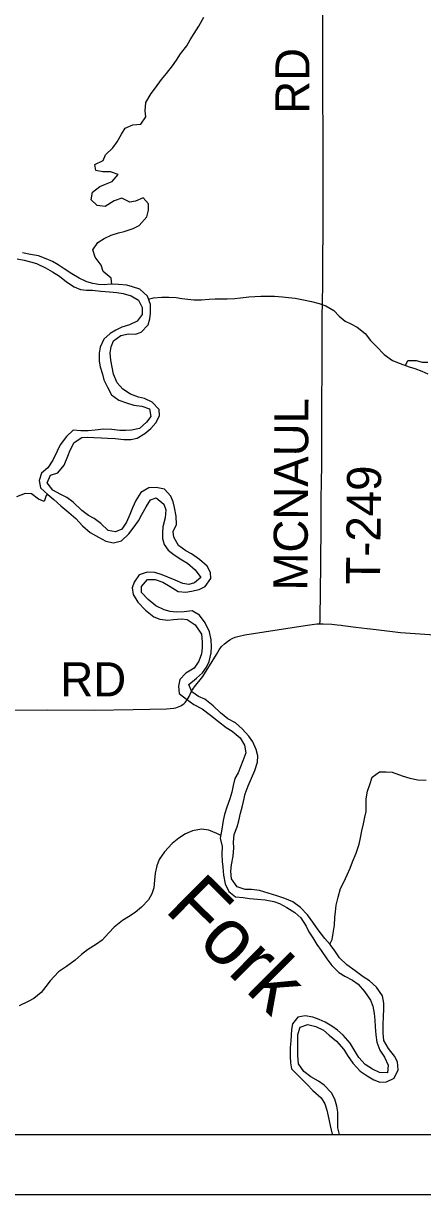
# Model space of a CAD drawing. Extents: x 0 to 70.2, y 0 to 31.4.
# Drawn here: x 5.768 to 6.434, y 14 to 15.952 of the extents above; entities that cross this region are included whole.
import ezdxf

# ---------------------------------------------------------------- set-up
doc = ezdxf.new("R2010")
doc.units = 0
for name, color, linetype in [('GM_X_Major_River', 7, 'Continuous'), ('GM_X_Major_River_Text', 7, 'Continuous'), ('GM_X_Minor_River', 7, 'Continuous'), ('GM_X_Section_Text', 7, 'Continuous'), ('GM_X_Township_Road', 7, 'Continuous'), ('GM_X_Township_Road_Text', 7, 'Continuous'), ('SH_Cut_Line', 7, 'Continuous'), ('SH_Data', 7, 'Continuous')]:
    doc.layers.add(name, color=color, linetype=linetype)

msp = doc.modelspace()

# ---------------------------------------------------------------- linework, layer by layer
at = {"layer": 'GM_X_Major_River'}
for points in [[(5.7581, 15.56), (5.7698, 15.5577), (5.78, 15.555), (5.7903, 15.552), (5.8051, 15.5448), (5.8172, 15.538), (5.8289, 15.5308), (5.8403, 15.5213), (5.8532, 15.5133), (5.8634, 15.5084), (5.8737, 15.5076), (5.8839, 15.5073), (5.8975, 15.5061), (5.9119, 15.505), (5.9245, 15.5035), (5.9347, 15.502), (5.948, 15.4982), (5.9601, 15.4906), (5.9665, 15.4784), (5.9665, 15.4671), (5.9582, 15.4557), (5.9453, 15.4496), (5.9328, 15.4458), (5.9225, 15.4409), (5.913, 15.4352), (5.9028, 15.4257), (5.8964, 15.4128), (5.8948, 15.4026), (5.8948, 15.3893), (5.8963, 15.3798), (5.9001, 15.3677), (5.9028, 15.3582), (5.9088, 15.3457), (5.9156, 15.3328), (5.9274, 15.3244), (5.9403, 15.3195), (5.9524, 15.3161), (5.9661, 15.3142), (5.9789, 15.3097), (5.9812, 15.2968), (5.9736, 15.2873), (5.9619, 15.2767), (5.9486, 15.274), (5.9391, 15.2736), (5.9293, 15.2736), (5.916, 15.2751), (5.9023, 15.2759), (5.8879, 15.2744), (5.8766, 15.2732), (5.8641, 15.2729), (5.8515, 15.274), (5.8402, 15.2638)], [(5.8659, 15.2619), (5.8754, 15.2626), (5.8857, 15.2622), (5.8985, 15.2615), (5.9084, 15.2607), (5.9217, 15.2603), (5.9357, 15.2585), (5.9478, 15.2585), (5.9581, 15.2611), (5.971, 15.2687), (5.9808, 15.277), (5.9892, 15.2865), (5.9956, 15.2983), (5.9949, 15.3085), (5.9831, 15.3207), (5.9702, 15.3271), (5.9604, 15.3294), (5.9471, 15.3343), (5.9342, 15.3423), (5.9248, 15.3533), (5.9187, 15.3677), (5.9164, 15.3794), (5.9142, 15.3908), (5.913, 15.403), (5.9146, 15.4132), (5.9187, 15.4231), (5.9309, 15.4318), (5.9438, 15.4348), (5.9551, 15.4344), (5.965, 15.4375), (5.9764, 15.45), (5.979, 15.4599), (5.9805, 15.4693), (5.9806, 15.4838), (5.9753, 15.4978), (5.9628, 15.5092), (5.9502, 15.5133), (5.9408, 15.5156), (5.9271, 15.5171), (5.9138, 15.5175), (5.9032, 15.5167), (5.8938, 15.5171), (5.8843, 15.5186), (5.8744, 15.5213), (5.8615, 15.5274), (5.8494, 15.5346), (5.8365, 15.5429), (5.8263, 15.5497), (5.8168, 15.5551), (5.8066, 15.56), (5.7937, 15.5649), (5.7804, 15.5672), (5.7668, 15.5695)], [(5.8402, 15.2638), (5.8299, 15.2497), (5.825, 15.2391), (5.8174, 15.2239), (5.8094, 15.2114), (5.7988, 15.2027), (5.7946, 15.1902), (5.7969, 15.178), (5.809, 15.1667), (5.8193, 15.1587), (5.831, 15.1481), (5.8443, 15.1367), (5.8556, 15.1268), (5.867, 15.1147), (5.8795, 15.1037), (5.8935, 15.0961), (5.9057, 15.0893), (5.9185, 15.0862), (5.9318, 15.0897), (5.9443, 15.1014), (5.9515, 15.1109), (5.9603, 15.123), (5.966, 15.1337), (5.9732, 15.1466), (5.9804, 15.1583), (5.9899, 15.1614), (6.0027, 15.1507), (6.0062, 15.1413), (6.005, 15.128), (6.0012, 15.1132), (6.0004, 15.1037), (6.0004, 15.0938), (6.0031, 15.0836), (6.0099, 15.0741), (6.0198, 15.0662), (6.0326, 15.0582), (6.0421, 15.0525), (6.0546, 15.0415), (6.0641, 15.0286), (6.0539, 15.0195), (6.0444, 15.0169), (6.0345, 15.0184), (6.0213, 15.0244), (6.0095, 15.029), (6, 15.0328), (5.9875, 15.0369), (5.9746, 15.0373), (5.9617, 15.0332), (5.953, 15.021), (5.95, 15.0112), (5.9515, 15.0005), (5.9591, 14.9873), (5.9719, 14.9744), (5.986, 14.963), (5.9958, 14.9592), (6.0091, 14.9577), (6.0186, 14.9584), (6.0318, 14.9596), (6.0413, 14.9584), (6.055, 14.9497), (6.0656, 14.9342), (6.0667, 14.9216), (6.0667, 14.9114), (6.0652, 14.9015), (6.061, 14.889), (6.053, 14.8773), (6.0394, 14.8689), (6.0295, 14.8587), (6.0268, 14.8477), (6.0284, 14.8352), (6.0405, 14.8257), (6.0526, 14.817), (6.0663, 14.8098), (6.0803, 14.7991), (6.0935, 14.7885), (6.1068, 14.7783), (6.1163, 14.7726), (6.1299, 14.7616), (6.1371, 14.7491), (6.1394, 14.7362), (6.1341, 14.7229), (6.1306, 14.713), (6.1265, 14.7032), (6.1212, 14.6933), (6.1181, 14.6819), (6.1158, 14.6709), (6.1128, 14.6599), (6.1075, 14.6459), (6.1037, 14.6334), (6.1014, 14.6235), (6.0991, 14.6091), (6.0968, 14.5939), (6.0999, 14.5803), (6.0995, 14.5674), (6.0999, 14.5553), (6.101, 14.5458), (6.1021, 14.5325), (6.1048, 14.5181), (6.1112, 14.5052), (6.1222, 14.4965), (6.1351, 14.495)], [(6.1487, 14.5086), (6.1381, 14.5086), (6.1249, 14.5128), (6.1154, 14.5261), (6.1146, 14.5393), (6.1154, 14.5499), (6.1184, 14.564), (6.1196, 14.578), (6.1188, 14.5875), (6.12, 14.6), (6.1249, 14.6129), (6.1279, 14.6232), (6.1306, 14.636), (6.1333, 14.6455), (6.1355, 14.655), (6.1382, 14.6679), (6.1435, 14.6812), (6.1541, 14.707), (6.1587, 14.721), (6.1591, 14.7316), (6.1568, 14.7419), (6.1508, 14.7544), (6.1443, 14.7639), (6.1333, 14.7764), (6.122, 14.7866), (6.1091, 14.7931), (6.097, 14.8029), (6.0848, 14.8147), (6.0708, 14.8257), (6.0602, 14.8302), (6.0492, 14.8382), (6.0443, 14.85), (6.0572, 14.861), (6.067, 14.8697), (6.0735, 14.8792), (6.078, 14.8887), (6.0815, 14.9031), (6.0819, 14.9133), (6.0815, 14.9247), (6.0785, 14.9383), (6.0716, 14.9528), (6.0622, 14.966), (6.0497, 14.9729), (6.0364, 14.9713), (6.0231, 14.971), (6.0133, 14.9721), (6.0034, 14.9747), (5.9894, 14.9812), (5.9765, 14.9918), (5.9655, 15.0036), (5.9651, 15.0134), (5.9754, 15.0252), (5.9883, 15.0252), (6.0012, 15.0206), (6.0133, 15.0138), (6.0265, 15.0055), (6.0391, 15.0043), (6.0489, 15.0059), (6.0614, 15.0085), (6.0717, 15.0134), (6.0808, 15.0271), (6.0804, 15.037), (6.0751, 15.0476), (6.0622, 15.0586), (6.0486, 15.0681), (6.0391, 15.073), (6.0273, 15.0817), (6.019, 15.0957), (6.0183, 15.1052), (6.0236, 15.117), (6.0232, 15.1306), (6.0206, 15.145), (6.0179, 15.1545), (6.0141, 15.1644), (6.0035, 15.1758), (5.9899, 15.1788), (5.9774, 15.178), (5.9645, 15.1701), (5.9561, 15.1572), (5.9504, 15.1447), (5.9459, 15.1337), (5.9402, 15.1211), (5.9326, 15.1094), (5.922, 15.1045), (5.9098, 15.1067), (5.8977, 15.1185), (5.8863, 15.1268), (5.8769, 15.1318), (5.8659, 15.1401), (5.8515, 15.1541), (5.8409, 15.1621), (5.831, 15.167), (5.8174, 15.1742), (5.8083, 15.1864), (5.8136, 15.1989), (5.8257, 15.2031), (5.8363, 15.2156), (5.8424, 15.2308), (5.8462, 15.2406), (5.8531, 15.2535), (5.8659, 15.2619)], [(6.2957, 14.1), (6.293, 14.1115), (6.2926, 14.1255), (6.2926, 14.1373), (6.2911, 14.1472), (6.2877, 14.1593), (6.2824, 14.1695), (6.2699, 14.1824), (6.2604, 14.1893), (6.2479, 14.1961), (6.2358, 14.2052), (6.227, 14.2181), (6.2263, 14.2317), (6.2259, 14.2454), (6.2263, 14.256), (6.2263, 14.2666), (6.2297, 14.2788), (6.2426, 14.2833), (6.2563, 14.2803), (6.2688, 14.2738), (6.2783, 14.2659), (6.2904, 14.2556), (6.3029, 14.2416), (6.3089, 14.2321), (6.318, 14.2188), (6.3298, 14.2056), (6.3419, 14.198), (6.3529, 14.1912), (6.3627, 14.1874), (6.3737, 14.1878), (6.3866, 14.1942), (6.3931, 14.2079), (6.392, 14.2211), (6.387, 14.2306), (6.3772, 14.2435), (6.3696, 14.2568), (6.3681, 14.2693), (6.3685, 14.2833), (6.3689, 14.2966), (6.3693, 14.3095), (6.3696, 14.319), (6.3674, 14.3315), (6.3575, 14.3459), (6.3458, 14.3565), (6.3348, 14.363), (6.3219, 14.3728), (6.3075, 14.3831), (6.2954, 14.3945), (6.2878, 14.4062), (6.2798, 14.4168), (6.2711, 14.4267), (6.2602, 14.4415), (6.2511, 14.454), (6.2423, 14.4661), (6.2306, 14.4787), (6.2177, 14.4878), (6.2045, 14.4938), (6.1912, 14.498), (6.1624, 14.5071), (6.1487, 14.5086)], [(6.1351, 14.495), (6.1453, 14.4938), (6.1586, 14.4923), (6.1715, 14.4912), (6.1863, 14.4885), (6.1957, 14.4851), (6.2079, 14.4783), (6.2211, 14.4703), (6.231, 14.4612), (6.2397, 14.4476), (6.2446, 14.4377), (6.251, 14.4282), (6.2575, 14.4168), (6.2647, 14.4066), (6.2742, 14.3929), (6.2829, 14.3819), (6.2946, 14.3702), (6.3045, 14.3641), (6.317, 14.3573), (6.3264, 14.3508), (6.3374, 14.3387), (6.3473, 14.3243), (6.3511, 14.3141), (6.3533, 14.3019), (6.3545, 14.2909), (6.3552, 14.2795), (6.356, 14.2663), (6.3579, 14.2541), (6.3628, 14.2409), (6.3704, 14.2291), (6.3768, 14.2158), (6.3756, 14.2029), (6.3624, 14.2037), (6.3506, 14.209), (6.3385, 14.217), (6.3279, 14.2287), (6.3215, 14.2386), (6.3135, 14.2522), (6.3018, 14.2659), (6.2923, 14.2742), (6.2828, 14.2807), (6.2718, 14.2875), (6.2616, 14.2917), (6.251, 14.2955), (6.2381, 14.2977), (6.226, 14.2958), (6.2172, 14.2845), (6.2157, 14.275), (6.2149, 14.2655), (6.2142, 14.256), (6.2134, 14.245), (6.2134, 14.2302), (6.2138, 14.2196), (6.2157, 14.2097), (6.2418, 14.1836), (6.2513, 14.1737), (6.2649, 14.1612), (6.271, 14.151), (6.2744, 14.1407), (6.2778, 14.1255), (6.2808, 14.1126), (6.2831, 14.1009), (6.2833, 14.1)]]:
    msp.add_lwpolyline(points, dxfattribs=at)
at = {"layer": 'GM_X_Minor_River'}
for points in [[(5.9159, 15.5174), (5.915, 15.5274), (5.9017, 15.5384), (5.8979, 15.549), (5.8881, 15.5623), (5.8843, 15.5748), (5.8923, 15.5869), (5.9029, 15.5934), (5.915, 15.5991), (5.9272, 15.6029), (5.9366, 15.6051), (5.9514, 15.6104), (5.9617, 15.6154), (5.9742, 15.6298), (5.9772, 15.6408), (5.9769, 15.6514), (5.9681, 15.6616), (5.9552, 15.656), (5.9458, 15.6544), (5.9325, 15.6609), (5.9196, 15.6567), (5.9048, 15.6472), (5.8912, 15.6484), (5.8817, 15.6582), (5.8836, 15.6707), (5.8957, 15.6802), (5.9052, 15.684), (5.9162, 15.6886), (5.9265, 15.7003), (5.9136, 15.7049), (5.9011, 15.7049), (5.8893, 15.7068), (5.8874, 15.717), (5.9014, 15.7235), (5.9056, 15.7329), (5.9178, 15.7447), (5.9246, 15.7546), (5.9322, 15.7678), (5.9379, 15.7773), (5.9508, 15.7834), (5.9644, 15.7845), (5.9724, 15.7963), (5.9716, 15.8065), (5.9724, 15.8206), (5.9815, 15.8354), (5.9887, 15.8448), (5.9986, 15.8589), (6.0069, 15.8687), (6.0168, 15.8813), (6.024, 15.8911), (6.0304, 15.9014), (6.0407, 15.915), (6.0464, 15.9249), (6.0532, 15.9355), (6.0608, 15.9476), (6.0691, 15.9624)], [(5.9773, 15.4924), (5.9855, 15.4948), (5.9995, 15.4959), (6.0109, 15.4959), (6.023, 15.4951), (6.0325, 15.4936), (6.0424, 15.4925), (6.0526, 15.4917), (6.0655, 15.4917), (6.0784, 15.4925), (6.0882, 15.4929), (6.1083, 15.4929), (6.1208, 15.4936), (6.1303, 15.4948), (6.1443, 15.4963), (6.1546, 15.497), (6.1641, 15.4974), (6.1769, 15.4978), (6.1872, 15.4974), (6.2004, 15.4967), (6.2103, 15.4955), (6.2217, 15.494), (6.2353, 15.4914), (6.2486, 15.4887), (6.2615, 15.4853), (6.2725, 15.4815), (6.2861, 15.4735), (6.2952, 15.4641), (6.3051, 15.4557), (6.3145, 15.4515), (6.3248, 15.4459), (6.3384, 15.4352), (6.3475, 15.4239), (6.357, 15.4136), (6.3699, 15.4003), (6.3839, 15.3901), (6.3968, 15.3852), (6.4115, 15.3799), (6.421, 15.3768), (6.4331, 15.3723), (6.443, 15.3681)], [(6.4056, 15.382), (6.4096, 15.3901), (6.4233, 15.3901), (6.4332, 15.3875), (6.443, 15.3878)], [(5.8082, 15.1675), (5.8064, 15.1651), (5.803, 15.1553), (5.7935, 15.1594), (5.7817, 15.1678), (5.7715, 15.1685), (5.7571, 15.1629)], [(6.2793, 14.4175), (6.2833, 14.4252), (6.2848, 14.4358), (6.2871, 14.4491), (6.2878, 14.4616), (6.2886, 14.4715), (6.2897, 14.4825), (6.2935, 14.4957), (6.2973, 14.5101), (6.3027, 14.5208), (6.3083, 14.5329), (6.3133, 14.5443), (6.3171, 14.5549), (6.3231, 14.5689), (6.3281, 14.5841), (6.3304, 14.5947), (6.3326, 14.6065), (6.3353, 14.6182), (6.338, 14.6289), (6.3399, 14.6387), (6.3399, 14.6596), (6.3422, 14.6725), (6.346, 14.6835), (6.3501, 14.696), (6.3623, 14.7047), (6.3733, 14.7047), (6.3831, 14.704), (6.3998, 14.6979), (6.4127, 14.6941), (6.426, 14.6915), (6.44, 14.6907)], [(6.0975, 14.5986), (6.0908, 14.6019), (6.0779, 14.6072), (6.0654, 14.6091), (6.0502, 14.6065), (6.0388, 14.6011), (6.0278, 14.5939), (6.0165, 14.5852), (6.0036, 14.5712), (5.9948, 14.5583), (5.9907, 14.548), (5.988, 14.5355), (5.9872, 14.5241), (5.9857, 14.5112), (5.9827, 14.5014), (5.977, 14.4915), (5.9652, 14.479), (5.9546, 14.4703), (5.9436, 14.4631), (5.9338, 14.4566), (5.9197, 14.4456), (5.911, 14.4361), (5.9, 14.424), (5.8905, 14.4172), (5.8753, 14.4077), (5.8655, 14.4001), (5.8549, 14.3906), (5.8405, 14.3804), (5.8268, 14.3713), (5.8128, 14.3565), (5.8059, 14.3466), (5.798, 14.3368), (5.7858, 14.3269), (5.7764, 14.3216), (5.7616, 14.3148)]]:
    msp.add_lwpolyline(points, dxfattribs=at)
at = {"layer": 'GM_X_Section_Text'}
msp.add_lwpolyline([(2.683, 14.1), (6.7623, 14.1)], dxfattribs=at)
at = {"layer": 'GM_X_Township_Road'}
for points in [[(6.2629, 14.9516), (6.2632, 14.9566), (6.2634, 14.9658), (6.2638, 14.9999), (6.2649, 15.1117), (6.2648, 15.1457), (6.2651, 15.158), (6.2654, 15.189), (6.2661, 15.2139), (6.2659, 15.2325), (6.2662, 15.3009), (6.2663, 15.3289), (6.2665, 15.3662), (6.2667, 15.4066), (6.2669, 15.4624), (6.2676, 15.5152), (6.2678, 15.5494), (6.2682, 15.6165), (6.2681, 15.6724), (6.2681, 15.7625), (6.2675, 15.837), (6.2676, 15.868), (6.2678, 15.9332), (6.2677, 15.9661)], [(5.731, 14.8073), (5.8086, 14.8078), (5.8862, 14.8077), (5.9514, 14.8085), (6.0072, 14.8096), (6.0133, 14.81), (6.0194, 14.8108), (6.0224, 14.8114), (6.0253, 14.8123), (6.0281, 14.8134), (6.0308, 14.8147), (6.0334, 14.8162), (6.0358, 14.8181), (6.0379, 14.8201), (6.0398, 14.8224), (6.0416, 14.8249), (6.0446, 14.8301), (6.049, 14.839), (6.0505, 14.8413), (6.0519, 14.844), (6.054, 14.8466), (6.0676, 14.8636), (6.0721, 14.8708), (6.0788, 14.8812), (6.0902, 14.9004), (6.0949, 14.908), (6.099, 14.9135), (6.1037, 14.918), (6.1087, 14.9218), (6.1127, 14.9249), (6.1165, 14.927), (6.1215, 14.9293), (6.128, 14.9309), (6.1376, 14.9331), (6.2023, 14.9431), (6.2421, 14.9489), (6.2577, 14.9511), (6.2629, 14.9516)], [(6.2629, 14.9516), (6.2682, 14.9513), (6.2827, 14.9507), (6.2917, 14.9498), (6.2981, 14.949), (6.3013, 14.9488), (6.3229, 14.9459), (6.3418, 14.9435), (6.3569, 14.9417), (6.397, 14.937), (6.4464, 14.9336), (6.4929, 14.9311), (6.5186, 14.9302)]]:
    msp.add_lwpolyline(points, dxfattribs=at)
at = {"layer": 'SH_Cut_Line'}
msp.add_lwpolyline([(2.1, 14.1), (6.7623, 14.1)], dxfattribs=at)
at = {"layer": 'SH_Data'}
for p, q in [((2.1, 14.1), (8.9, 14.1)), ((2, 14), (9, 14))]:
    msp.add_line(p, q, dxfattribs=at)

# ---------------------------------------------------------------- texts
at = {"layer": 'GM_X_Major_River_Text'}
msp.add_text('Fork', height=0.09473, rotation=315.223, dxfattribs=at).set_placement((6.0022, 14.4738))
at = {"layer": 'GM_X_Township_Road_Text'}
for s, rotation, p in [('RD', 90, (6.2455, 15.8015)), ('MCNAUL', 89.6839, (6.2421, 15.0067)), ('T-249', 89.4391, (6.3631, 15.0164)), ('RD', 359.9982, (5.8301, 14.8305))]:
    msp.add_text(s, height=0.05682, rotation=rotation, dxfattribs=at).set_placement(p)

doc.saveas('drawing.dxf')
